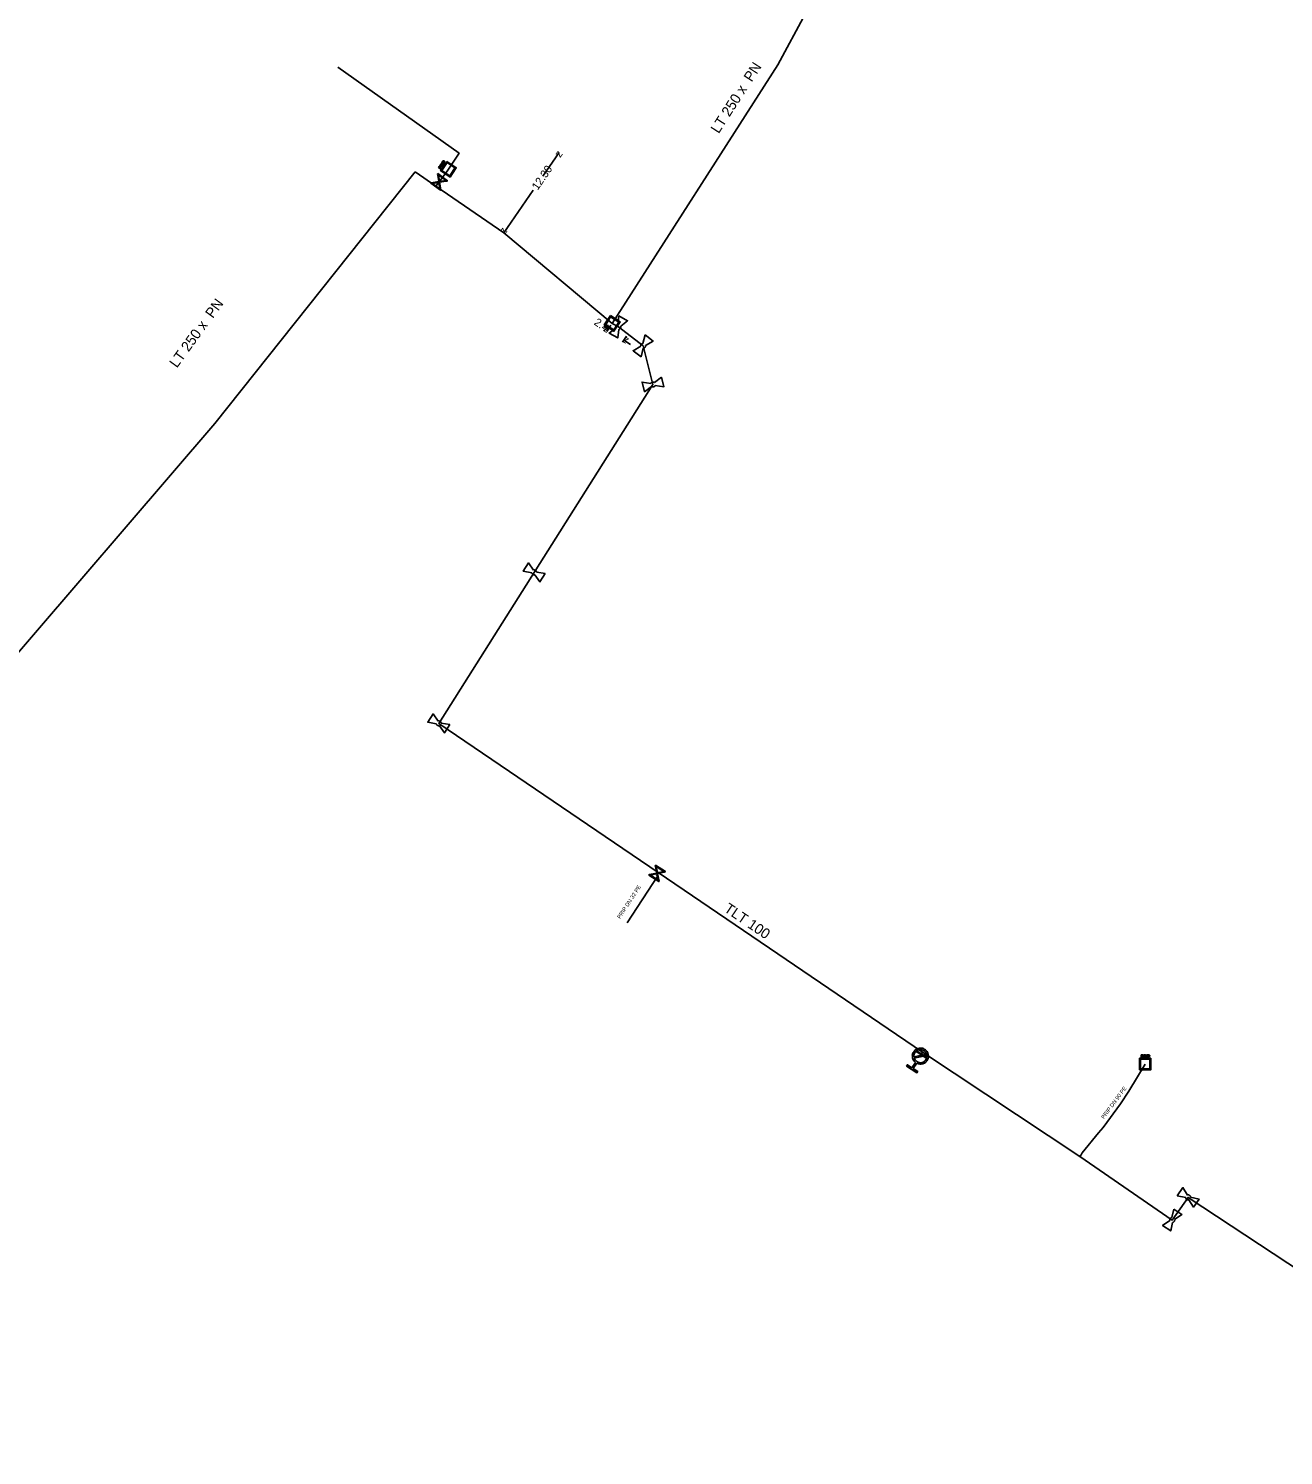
# Model space of a CAD drawing. Extents: x -643544 to -637295, y -1119190 to -1111715.
# Drawn here: x -641787.1 to -641628.7, y -1116222.4 to -1116042.4 of the extents above; entities that cross this region are included whole.
import ezdxf

# ---------------------------------------------------------------- set-up
doc = ezdxf.new("R2010")
doc.units = 0
for name, color, linetype in [('Default', 7, 'Continuous'), ('VP Hydrant', 7, 'Continuous'), ('VP Kótování', 7, 'Continuous'), ('VP Lomový bod', 7, 'Continuous'), ('VP Popis přípojky', 7, 'Continuous'), ('VP Přípojka', 7, 'Continuous'), ('VP Řad', 7, 'Continuous'), ('VP Řad - popis', 7, 'Continuous'), ('VP Šachta', 7, 'Continuous'), ('VP Šoupě', 7, 'Continuous')]:
    doc.layers.add(name, color=color, linetype=linetype)

msp = doc.modelspace()

# ---------------------------------------------------------------- linework, layer by layer
at = {"layer": 'Default'}
for points in [[(-641735.29, -1116059.77), (-641735.27, -1116059.74), (-641735.26, -1116059.73), (-641735.24, -1116059.71), (-641735.22, -1116059.7), (-641735.2, -1116059.69), (-641735.17, -1116059.69), (-641735.15, -1116059.7), (-641735.13, -1116059.71), (-641735.09, -1116059.74), (-641735.08, -1116059.78), (-641735.07, -1116059.82), (-641735.11, -1116059.88)], [(-641735.15, -1116059.86), (-641735.12, -1116059.82), (-641735.12, -1116059.8), (-641735.13, -1116059.77), (-641735.15, -1116059.75), (-641735.17, -1116059.74), (-641735.19, -1116059.74), (-641735.21, -1116059.74), (-641735.23, -1116059.75), (-641735.24, -1116059.76), (-641735.25, -1116059.79)], [(-641735.1, -1116059.48), (-641735.07, -1116059.44), (-641735.05, -1116059.43), (-641735.03, -1116059.41), (-641735, -1116059.41), (-641734.97, -1116059.42), (-641734.95, -1116059.43), (-641734.91, -1116059.45), (-641734.91, -1116059.49), (-641734.9, -1116059.52), (-641734.92, -1116059.57), (-641734.9, -1116059.56), (-641734.89, -1116059.56), (-641734.86, -1116059.55), (-641734.83, -1116059.55)], [(-641734.97, -1116059.58), (-641734.95, -1116059.55), (-641734.95, -1116059.53), (-641734.94, -1116059.52), (-641734.95, -1116059.5), (-641734.96, -1116059.48), (-641734.97, -1116059.47), (-641734.99, -1116059.46), (-641735.02, -1116059.47), (-641735.04, -1116059.47), (-641735.06, -1116059.5)], [(-641734.84, -1116059.6), (-641734.87, -1116059.6), (-641734.9, -1116059.6), (-641734.92, -1116059.6), (-641734.93, -1116059.61), (-641734.94, -1116059.61), (-641734.95, -1116059.62), (-641734.96, -1116059.63), (-641734.97, -1116059.64)], [(-641734.84, -1116059.1), (-641734.82, -1116059.08), (-641734.81, -1116059.06), (-641734.79, -1116059.04), (-641734.77, -1116059.03), (-641734.75, -1116059.03), (-641734.72, -1116059.03), (-641734.7, -1116059.03), (-641734.68, -1116059.05), (-641734.64, -1116059.07), (-641734.63, -1116059.12), (-641734.62, -1116059.16), (-641734.66, -1116059.22)], [(-641734.7, -1116059.2), (-641734.67, -1116059.16), (-641734.67, -1116059.13), (-641734.68, -1116059.11), (-641734.7, -1116059.09), (-641734.72, -1116059.08), (-641734.74, -1116059.08), (-641734.76, -1116059.08), (-641734.78, -1116059.09), (-641734.79, -1116059.1), (-641734.8, -1116059.13)], [(-641712.96, -1116080.11), (-641712.98, -1116080.06), (-641712.98, -1116080), (-641712.98, -1116079.92), (-641712.94, -1116079.85), (-641712.9, -1116079.77), (-641712.83, -1116079.73), (-641712.78, -1116079.7), (-641712.73, -1116079.69)], [(-641712.37, -1116079.89), (-641712.36, -1116079.94), (-641712.36, -1116080), (-641712.36, -1116080.08), (-641712.4, -1116080.15), (-641712.44, -1116080.23), (-641712.51, -1116080.27), (-641712.56, -1116080.3), (-641712.61, -1116080.31)], [(-641709.85, -1116082.45), (-641709.86, -1116082.4), (-641709.85, -1116082.35), (-641709.84, -1116082.27), (-641709.79, -1116082.2), (-641709.74, -1116082.14), (-641709.66, -1116082.1), (-641709.61, -1116082.08), (-641709.56, -1116082.08)], [(-641709.23, -1116082.33), (-641709.22, -1116082.38), (-641709.23, -1116082.43), (-641709.24, -1116082.51), (-641709.29, -1116082.58), (-641709.34, -1116082.64), (-641709.42, -1116082.68), (-641709.47, -1116082.7), (-641709.52, -1116082.7)], [(-641708.58, -1116087.13), (-641708.56, -1116087.08), (-641708.52, -1116087.05), (-641708.46, -1116086.99), (-641708.38, -1116086.97), (-641708.3, -1116086.95), (-641708.21, -1116086.97), (-641708.16, -1116086.98), (-641708.12, -1116087.01)], [(-641708.02, -1116087.41), (-641708.04, -1116087.46), (-641708.08, -1116087.49), (-641708.14, -1116087.55), (-641708.22, -1116087.57), (-641708.3, -1116087.59), (-641708.38, -1116087.57), (-641708.44, -1116087.56), (-641708.48, -1116087.53)], [(-641723.38, -1116110.68), (-641723.33, -1116110.66), (-641723.28, -1116110.67), (-641723.19, -1116110.67), (-641723.12, -1116110.71), (-641723.06, -1116110.76), (-641723.01, -1116110.83), (-641722.99, -1116110.88), (-641722.98, -1116110.93)], [(-641723.2, -1116111.28), (-641723.25, -1116111.29), (-641723.3, -1116111.29), (-641723.39, -1116111.29), (-641723.46, -1116111.24), (-641723.53, -1116111.2), (-641723.57, -1116111.12), (-641723.59, -1116111.08), (-641723.6, -1116111.02)], [(-641735.25, -1116130.33), (-641735.3, -1116130.35), (-641735.35, -1116130.34), (-641735.44, -1116130.34), (-641735.51, -1116130.29), (-641735.58, -1116130.25), (-641735.62, -1116130.18), (-641735.64, -1116130.13), (-641735.65, -1116130.08)], [(-641735.43, -1116129.73), (-641735.38, -1116129.72), (-641735.33, -1116129.72), (-641735.24, -1116129.72), (-641735.17, -1116129.77), (-641735.1, -1116129.81), (-641735.06, -1116129.89), (-641735.04, -1116129.93), (-641735.03, -1116129.98)], [(-641675.16, -1116172.8), (-641675.45, -1116172.57), (-641675.52, -1116172.22), (-641675.6, -1116171.81), (-641675.38, -1116171.46), (-641675.15, -1116171.12), (-641674.75, -1116171.03), (-641674.34, -1116170.95), (-641673.99, -1116171.17), (-641673.65, -1116171.4), (-641673.56, -1116171.8), (-641673.47, -1116172.21), (-641673.7, -1116172.55), (-641673.93, -1116172.9), (-641674.33, -1116172.99), (-641674.69, -1116173.07), (-641675.01, -1116172.9)], [(-641673.77, -1116171.75), (-641673.85, -1116171.49), (-641674.1, -1116171.33), (-641674.38, -1116171.15), (-641674.71, -1116171.22), (-641675.04, -1116171.29), (-641675.22, -1116171.57), (-641675.38, -1116171.81), (-641675.35, -1116172.09)], [(-641675.31, -1116172.27), (-641675.23, -1116172.53), (-641674.98, -1116172.69), (-641674.7, -1116172.88), (-641674.37, -1116172.81), (-641674.04, -1116172.74), (-641673.86, -1116172.46), (-641673.7, -1116172.21), (-641673.73, -1116171.93)], [(-641646.53, -1116171.86), (-641646.49, -1116171.86), (-641646.47, -1116171.87), (-641646.45, -1116171.87), (-641646.43, -1116171.89), (-641646.41, -1116171.9), (-641646.4, -1116171.92), (-641646.39, -1116171.94), (-641646.39, -1116171.97), (-641646.39, -1116172.02), (-641646.42, -1116172.05), (-641646.45, -1116172.08), (-641646.52, -1116172.08)], [(-641646.52, -1116172.04), (-641646.48, -1116172.04), (-641646.46, -1116172.02), (-641646.44, -1116172), (-641646.44, -1116171.97), (-641646.44, -1116171.95), (-641646.45, -1116171.93), (-641646.46, -1116171.92), (-641646.48, -1116171.91), (-641646.49, -1116171.91), (-641646.53, -1116171.91)], [(-641646.2, -1116172.02), (-641646.16, -1116172.02), (-641646.14, -1116172.02), (-641646.13, -1116172.01), (-641646.12, -1116172), (-641646.11, -1116171.98), (-641646.11, -1116171.96), (-641646.11, -1116171.94), (-641646.13, -1116171.92), (-641646.14, -1116171.91), (-641646.18, -1116171.91)], [(-641646.19, -1116171.86), (-641646.14, -1116171.86), (-641646.11, -1116171.87), (-641646.09, -1116171.88), (-641646.07, -1116171.91), (-641646.06, -1116171.93), (-641646.06, -1116171.96), (-641646.06, -1116172), (-641646.08, -1116172.03), (-641646.11, -1116172.05), (-641646.16, -1116172.06), (-641646.14, -1116172.07), (-641646.13, -1116172.08), (-641646.11, -1116172.1), (-641646.09, -1116172.13)], [(-641645.73, -1116171.87), (-641645.69, -1116171.87), (-641645.67, -1116171.87), (-641645.65, -1116171.87), (-641645.63, -1116171.89), (-641645.61, -1116171.9), (-641645.6, -1116171.92), (-641645.59, -1116171.94), (-641645.59, -1116171.97), (-641645.59, -1116172.02), (-641645.62, -1116172.05), (-641645.65, -1116172.08), (-641645.72, -1116172.08)], [(-641645.72, -1116172.04), (-641645.68, -1116172.04), (-641645.66, -1116172.02), (-641645.64, -1116172), (-641645.64, -1116171.97), (-641645.64, -1116171.95), (-641645.65, -1116171.93), (-641645.66, -1116171.92), (-641645.68, -1116171.91), (-641645.69, -1116171.91), (-641645.72, -1116171.91)], [(-641646.14, -1116172.15), (-641646.16, -1116172.12), (-641646.17, -1116172.1), (-641646.18, -1116172.08), (-641646.19, -1116172.08), (-641646.2, -1116172.07), (-641646.22, -1116172.07), (-641646.22, -1116172.06), (-641646.24, -1116172.06)], [(-641640.66, -1116190.14), (-641640.72, -1116190.16), (-641640.77, -1116190.15), (-641640.85, -1116190.14), (-641640.92, -1116190.1), (-641640.99, -1116190.05), (-641641.02, -1116189.97), (-641641.05, -1116189.92), (-641641.05, -1116189.87)], [(-641640.82, -1116189.54), (-641640.77, -1116189.52), (-641640.71, -1116189.53), (-641640.63, -1116189.54), (-641640.56, -1116189.58), (-641640.49, -1116189.63), (-641640.46, -1116189.71), (-641640.43, -1116189.76), (-641640.43, -1116189.81)], [(-641643.05, -1116192.77), (-641643.07, -1116192.72), (-641643.06, -1116192.66), (-641643.05, -1116192.58), (-641643.01, -1116192.51), (-641642.96, -1116192.45), (-641642.88, -1116192.41), (-641642.84, -1116192.38), (-641642.78, -1116192.38)], [(-641642.45, -1116192.61), (-641642.43, -1116192.66), (-641642.44, -1116192.71), (-641642.45, -1116192.8), (-641642.49, -1116192.87), (-641642.54, -1116192.93), (-641642.61, -1116192.97), (-641642.66, -1116193), (-641642.72, -1116193)]]:
    msp.add_open_spline(points, degree=3, dxfattribs=at)
at = {"layer": 'VP Hydrant'}
for points in [[(-641675.35, -1116172.09), (-641673.77, -1116171.75)], [(-641673.73, -1116171.93), (-641675.31, -1116172.27)], [(-641675.01, -1116172.9), (-641675.45, -1116173.58), (-641674.87, -1116173.96), (-641674.97, -1116174.11), (-641676.29, -1116173.26), (-641676.18, -1116173.11), (-641675.61, -1116173.48), (-641675.16, -1116172.8)]]:
    msp.add_lwpolyline(points, dxfattribs=at)
at = {"layer": 'VP Kótování'}
for points in [[(-641722.19, -1116060.98), (-641720.14, -1116058.01)], [(-641723.41, -1116062.73), (-641727.13, -1116068.12)], [(-641714.5, -1116079.94), (-641713.96, -1116080.31)], [(-641713.62, -1116079.8), (-641714.13, -1116080.56)], [(-641711.63, -1116081.16), (-641712.15, -1116081.91)], [(-641711.15, -1116082.22), (-641711.98, -1116081.66)]]:
    msp.add_lwpolyline(points, dxfattribs=at)
at = {"layer": 'VP Lomový bod'}
for points in [[(-641712.61, -1116080.31), (-641712.74, -1116081.4), (-641713.83, -1116080.78), (-641712.96, -1116080.11)], [(-641712.73, -1116079.69), (-641712.6, -1116078.6)], [(-641712.6, -1116078.6), (-641711.51, -1116079.22), (-641712.37, -1116079.89)], [(-641709.56, -1116082.08), (-641709.28, -1116081.02)], [(-641709.28, -1116081.02), (-641708.28, -1116081.78), (-641709.23, -1116082.33)], [(-641709.52, -1116082.7), (-641709.8, -1116083.76), (-641710.8, -1116083), (-641709.85, -1116082.45)], [(-641708.48, -1116087.53), (-641709.36, -1116088.18), (-641709.67, -1116086.97), (-641708.58, -1116087.13)], [(-641708.12, -1116087.01), (-641707.24, -1116086.36)], [(-641707.24, -1116086.36), (-641706.93, -1116087.57), (-641708.02, -1116087.41)], [(-641723.6, -1116111.02), (-641724.68, -1116110.84), (-641724.01, -1116109.78), (-641723.38, -1116110.68)], [(-641721.9, -1116111.12), (-641722.57, -1116112.17), (-641723.2, -1116111.28)], [(-641722.98, -1116110.93), (-641721.9, -1116111.12)], [(-641735.65, -1116130.08), (-641736.73, -1116129.89), (-641736.06, -1116128.83), (-641735.43, -1116129.73)], [(-641733.95, -1116130.17), (-641734.62, -1116131.23), (-641735.25, -1116130.33)], [(-641735.03, -1116129.98), (-641733.95, -1116130.17)], [(-641642.12, -1116189.63), (-641641.4, -1116188.61), (-641640.82, -1116189.54)], [(-641641.05, -1116189.87), (-641642.12, -1116189.63)], [(-641640.43, -1116189.81), (-641639.36, -1116190.05), (-641640.08, -1116191.07), (-641640.66, -1116190.14)], [(-641642.78, -1116192.38), (-641642.56, -1116191.31)], [(-641642.56, -1116191.31), (-641641.53, -1116192.01), (-641642.45, -1116192.61)], [(-641642.72, -1116193), (-641642.94, -1116194.07), (-641643.97, -1116193.37), (-641643.05, -1116192.77)]]:
    msp.add_lwpolyline(points, dxfattribs=at)
at = {"layer": 'VP Přípojka'}
for points in [[(-641735.69, -1116062.25), (-641735.29, -1116061.71), (-641734.3, -1116060.35), (-641734.13, -1116060.09), (-641732.77, -1116058.08), (-641748.08, -1116047.24)], [(-641707.65, -1116148.84), (-641707.77, -1116148.94), (-641707.87, -1116149.15), (-641707.7, -1116149.18), (-641707.69, -1116149.28), (-641711.55, -1116155.2)], [(-641674.29, -1116171.5), (-641674.41, -1116171.81), (-641674.54, -1116172.01)], [(-641646.15, -1116173.01), (-641648.24, -1116176.43), (-641649.28, -1116178.04), (-641651.46, -1116181), (-641652.06, -1116181.71), (-641654.11, -1116184.21), (-641654.26, -1116184.48), (-641654.42, -1116184.67)]]:
    msp.add_lwpolyline(points, dxfattribs=at)
at = {"layer": 'VP Řad'}
for points in [[(-641713.45, -1116079.56), (-641692.55, -1116046.94), (-641685.55, -1116033.93), (-641687.15, -1116027.36), (-641684.87, -1116024.47)], [(-641738.32, -1116060.45), (-641763.62, -1116092.18), (-641791.9, -1116125.08), (-641809.9, -1116147.66), (-641839.25, -1116184.78)], [(-641713.45, -1116079.56), (-641727.13, -1116068.12), (-641735.69, -1116062.25), (-641738.32, -1116060.45)], [(-641713.45, -1116079.56), (-641712.67, -1116080), (-641709.54, -1116082.39), (-641708.3, -1116087.27), (-641735.34, -1116130.03), (-641707.65, -1116148.84), (-641674.29, -1116171.5), (-641654.42, -1116184.67), (-641642.75, -1116192.69), (-641640.74, -1116189.84), (-641592.38, -1116221.71), (-641591.48, -1116222.4)]]:
    msp.add_lwpolyline(points, dxfattribs=at)
at = {"layer": 'VP Šachta'}
for points in [[(-641735.07, -1116060.08), (-641735.37, -1116059.88), (-641735.29, -1116059.77)], [(-641735.25, -1116059.79), (-641735.31, -1116059.87), (-641735.2, -1116059.94)], [(-641735.2, -1116059.94), (-641735.15, -1116059.86)], [(-641734.89, -1116059.82), (-641735.19, -1116059.61), (-641735.1, -1116059.48)], [(-641735.11, -1116059.88), (-641735.16, -1116059.96), (-641735.04, -1116060.04), (-641735.07, -1116060.08)], [(-641735.06, -1116059.5), (-641735.13, -1116059.6), (-641735.03, -1116059.66)], [(-641734.33, -1116059.11), (-641733.13, -1116059.92), (-641733.92, -1116061.09), (-641735.12, -1116060.28), (-641734.33, -1116059.11)], [(-641735.03, -1116059.66), (-641734.97, -1116059.58)], [(-641734.97, -1116059.64), (-641735, -1116059.69), (-641734.86, -1116059.78), (-641734.89, -1116059.82)], [(-641734.69, -1116059.52), (-641734.98, -1116059.31), (-641734.96, -1116059.28), (-641734.66, -1116059.48), (-641734.69, -1116059.52)], [(-641734.96, -1116060.25), (-641733.96, -1116060.92), (-641733.3, -1116059.95), (-641734.3, -1116059.27), (-641734.96, -1116060.25)], [(-641734.62, -1116059.42), (-641734.92, -1116059.22), (-641734.84, -1116059.1)], [(-641734.8, -1116059.13), (-641734.86, -1116059.2), (-641734.75, -1116059.27)], [(-641734.83, -1116059.55), (-641734.71, -1116059.55), (-641734.75, -1116059.6), (-641734.84, -1116059.6)], [(-641734.75, -1116059.27), (-641734.7, -1116059.2)], [(-641734.66, -1116059.22), (-641734.71, -1116059.3), (-641734.59, -1116059.38), (-641734.62, -1116059.42)], [(-641713.68, -1116078.57), (-641712.45, -1116079.36), (-641713.22, -1116080.55), (-641714.44, -1116079.76), (-641713.68, -1116078.57)], [(-641714.27, -1116079.73), (-641713.26, -1116080.38), (-641712.62, -1116079.39), (-641713.64, -1116078.74), (-641714.27, -1116079.73)], [(-641646.66, -1116172.22), (-641646.66, -1116171.86), (-641646.53, -1116171.86)], [(-641646.53, -1116171.91), (-641646.62, -1116171.91), (-641646.62, -1116172.04)], [(-641646.34, -1116172.22), (-641646.34, -1116171.86), (-641646.19, -1116171.86)], [(-641646.18, -1116171.91), (-641646.3, -1116171.91), (-641646.3, -1116172.02)], [(-641645.98, -1116172.23), (-641645.98, -1116171.87), (-641645.93, -1116171.87), (-641645.93, -1116172.23), (-641645.98, -1116172.23)], [(-641645.86, -1116172.23), (-641645.86, -1116171.87), (-641645.73, -1116171.87)], [(-641645.72, -1116171.91), (-641645.82, -1116171.91), (-641645.82, -1116172.04)], [(-641645.44, -1116172.29), (-641645.44, -1116173.74), (-641646.86, -1116173.74), (-641646.86, -1116172.29), (-641645.44, -1116172.29)], [(-641646.74, -1116172.41), (-641646.74, -1116173.62), (-641645.56, -1116173.62), (-641645.56, -1116172.41), (-641646.74, -1116172.41)], [(-641646.52, -1116172.08), (-641646.62, -1116172.08), (-641646.62, -1116172.22), (-641646.66, -1116172.22)], [(-641646.62, -1116172.04), (-641646.52, -1116172.04)], [(-641646.24, -1116172.06), (-641646.3, -1116172.06), (-641646.3, -1116172.22), (-641646.34, -1116172.22)], [(-641646.3, -1116172.02), (-641646.2, -1116172.02)], [(-641646.09, -1116172.13), (-641646.03, -1116172.22), (-641646.09, -1116172.22), (-641646.14, -1116172.15)], [(-641645.72, -1116172.08), (-641645.82, -1116172.08), (-641645.82, -1116172.23), (-641645.86, -1116172.23)], [(-641645.82, -1116172.04), (-641645.72, -1116172.04)]]:
    msp.add_lwpolyline(points, dxfattribs=at)
at = {"layer": 'VP Šoupě'}
for points in [[(-641735.46, -1116060.66), (-641734.25, -1116061.55), (-641734.28, -1116061.6), (-641734.41, -1116061.62), (-641735.24, -1116061.75), (-641735.09, -1116062.71), (-641735.13, -1116062.76), (-641736.34, -1116061.88), (-641736.3, -1116061.82), (-641735.34, -1116061.67), (-641735.47, -1116060.84), (-641735.5, -1116060.72), (-641735.46, -1116060.66)], [(-641735.2, -1116062.59), (-641735.33, -1116061.76), (-641736.16, -1116061.89), (-641735.2, -1116062.59)], [(-641735.39, -1116060.83), (-641735.26, -1116061.66), (-641734.43, -1116061.53), (-641735.39, -1116060.83)], [(-641707.99, -1116147.9), (-641706.73, -1116148.72), (-641706.77, -1116148.78), (-641706.89, -1116148.8), (-641707.72, -1116148.97), (-641707.51, -1116149.92), (-641707.55, -1116149.98), (-641708.81, -1116149.16), (-641708.77, -1116149.1), (-641707.82, -1116148.91), (-641708, -1116148.08), (-641708.03, -1116147.96), (-641707.99, -1116147.9)], [(-641707.91, -1116148.07), (-641707.73, -1116148.89), (-641706.92, -1116148.71), (-641707.91, -1116148.07)], [(-641707.63, -1116149.82), (-641707.8, -1116148.99), (-641708.63, -1116149.17), (-641707.63, -1116149.82)], [(-641673.81, -1116172.26), (-641675.06, -1116171.44), (-641675.01, -1116171.36), (-641673.76, -1116172.18), (-641673.81, -1116172.26)]]:
    msp.add_lwpolyline(points, dxfattribs=at)

# ---------------------------------------------------------------- texts
at = {"layer": 'VP Kótování'}
for s, rotation, p in [('z', 55.3355, (-641720.01, -1116058.71)), ('12.30', 55.3355, (-641722.85, -1116062.81)), ('z', 235.3355, (-641727.26, -1116067.43)), ('2.4', 325.7275, (-641715.83, -1116079.64)), ('z', 325.7274, (-641714.66, -1116080.44)), ('z', 145.7275, (-641711.28, -1116081.53))]:
    msp.add_text(s, height=1, rotation=rotation, dxfattribs=at).set_placement(p)
at = {"layer": 'VP Popis přípojky'}
for s, rotation, p in [('PRIP DN 32 PE', 56.893, (-641712.44, -1116154.73)), ('PRIP DN 90 PE', 53.6309, (-641651.36, -1116179.99))]:
    msp.add_text(s, height=0.5, rotation=rotation, dxfattribs=at).set_placement(p)
at = {"layer": 'VP Řad - popis'}
for s, rotation, p in [('LT 250 x  PN ', 57.33, (-641700.01, -1116055.69)), ('LT 250 x  PN ', 54.084, (-641768.4, -1116085.26)), ('TLT 100', 325.8134, (-641699.43, -1116153.68))]:
    msp.add_text(s, height=1.3, rotation=rotation, dxfattribs=at).set_placement(p)

doc.saveas('drawing.dxf')
